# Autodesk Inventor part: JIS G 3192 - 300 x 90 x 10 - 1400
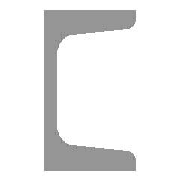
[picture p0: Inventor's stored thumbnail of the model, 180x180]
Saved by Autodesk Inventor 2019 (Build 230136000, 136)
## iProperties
_CCFamilyMember: 12
_CCFamilyDisplayName: JIS G 3192 - U 形熱間圧延鋼
_FrameMemberDoc: Frame Member File
_Version: 15.0.0
_GetPNFromCC: 1
Created: 2017-02
Part Number: JIS G 3192 - 300 x 90 x 10 - 1400
Material: 鋼、軟鋼
Description: U 形熱間圧延鋼
Document SubType Name: Modeling
Standard: JIS
Designer: shimont
Standard Revision: 2014
Standards Organization: JIS
Language: ja-JP
Size Designation: 300 x 90 x 10
Categories: <MemberInstance><Categories><Category DisplayName="形鋼" InternalName="089c4875-fa83-4c05-b084-43b9cc11f5ed" Mnemonic="GRDR"><CategoryParameter DisplayName="長さ単位ご
Stock Number: 300 x 90 x 10
Density: 7.85 g/cm^3
Appearance: 半つや出し
Mass: 61264.1 g
Surface Area: 12805.5 cm^2
Volume: 7804.34 cm^3
IsCustomPart: 1
G_L: 1400.000 mm
G_W: 90.000 mm
G_H: 300.000 mm
Author: shimont
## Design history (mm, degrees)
node "開始平面"
node "終了平面"
sketch "スケッチ"
  geometry: L1 (-23.4, 0)-(-23.4, 150); L2 (-23.4, 150)-(66.6, 150); L3 (66.6, 150)-(66.6, 146.705); L4 (57.928, 137.241)-(3.944, 132.518); L5 (-13.4, 113.59)-(-13.4, 0); L6 (-13.4, 0)-(-23.4, 0); L7 (26.6, 150)-(26.6, 134.5); L8 (66.6, 138)-(66.6, 134.5); L9 (66.6, 134.5)-(26.6, 134.5); L10 (0, 15)-(0, -27); L11 (-5.539, 0)-(16.007, 0); L12 (-23.4, 0)-(-23.4, -150); L13 (-23.4, -150)-(66.6, -150); L14 (66.6, -150)-(66.6, -146.705); L15 (57.928, -137.241)-(3.944, -132.518); L16 (-13.4, -113.59)-(-13.4, 0); L17 (0, 210)-(0, -210) reference; L18 (-41.768, 0)-(86.808, 0) reference; A1 r 19 centre (5.6, 113.59) between (3.944, 132.518) and (-13.4, 113.59); A2 r 19 centre (5.6, -113.59) between (-13.4, -113.59) and (3.944, -132.518); A3 r 9.5 centre (57.1, 146.705) between (57.928, 137.241) and (66.6, 146.705); A4 r 9.5 centre (57.1, -146.705) between (66.6, -146.705) and (57.928, -137.241); 5 further points
  constraints: 32 end point, 12 point on line, 8 point on circle, 8 tangent, 6 symmetric about line, 4 centre point, 4 parallel, 3 collinear, 3 perpendicular, 2 equal radius, 5 other
  dimensions: "d0" = 10 distance between parallel lines of L1 L5 (= G_T); "d1" = 150 distance between parallel lines of L6 L2 (= 0.5 x G_H); "d2" = 90 distance between parallel lines of L3 L1 (= G_W); "d3" = 15.5 distance of L2.end L8.end (= G_T1); "d4" = 40 distance of L7.start L2.end (= G_C); "d5" = 3.4996 distance of L8.start L8.end (computed from G_NG, G_C); "d23" = 19 radius of A1 (= G_IR); "d24" = 9.5 radius of A3 (= G_ER); "d25" = 23.4 distance between parallel lines of L10 L12 (= ey)
extrude "ボディ" new body sketch "スケッチ" stored distance "d6" = 1400 (= G_L); taper "d7" = 0 deg
node "Driven Length"
  sketch "Sketch3"
    geometry: L1 (0, 0)-(10, 0) reference
    constraints: 2 end point, 1 horizontal
  workplane "Work Plane3"
  sketch "Sketch4"
    geometry: L1 (-2, 0)-(12, 0) reference; L2 (-2, 1400)-(12, 1400) reference
    dimensions: "d29" = 1400 distance between parallel lines of L1 L2 (derived)
body "Solid1"
other parameters: "G_W" = 90 [user parameter; used in 1 equation term], "G_H" = 300 [user parameter; used in 1 equation term], "G_T" = 10 [user parameter; used in 1 equation term], "G_T1" = 15.5 [user parameter; used in 1 equation term], "G_NG" = 0.8749 [user parameter; used in 1 equation term], "G_ER" = 9.5 [user parameter; used in 1 equation term], "G_IR" = 19 [user parameter; used in 1 equation term], "G_C" = 40 [user parameter; used in 2 equation terms], "G_L" = 1400 (= d29) [user parameter; used in 1 equation term], "ey" = 23.4 [user parameter; used in 1 equation term], "G_OFFSET_START" = 0 [user parameter; used in 1 equation term], "G_OFFSET_END" = 0 [user parameter; used in 1 equation term], "d26" = 0 (computed from G_OFFSET_START), "d28" = 90 deg
